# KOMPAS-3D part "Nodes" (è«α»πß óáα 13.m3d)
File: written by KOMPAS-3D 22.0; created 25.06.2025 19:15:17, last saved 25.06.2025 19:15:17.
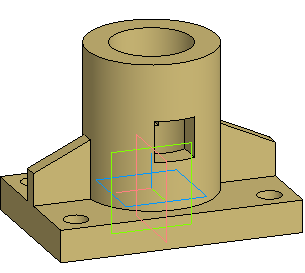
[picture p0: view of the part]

Document properties: Автор: Helen; Полное имя файла: D:\MY\WORK\MPEI\ППЭ_2025-2026\Варианты\Вар 13 СБ\Корпус вар 13.m3d

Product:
- Part/product: Nodes

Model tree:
1. Операция без истории:1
